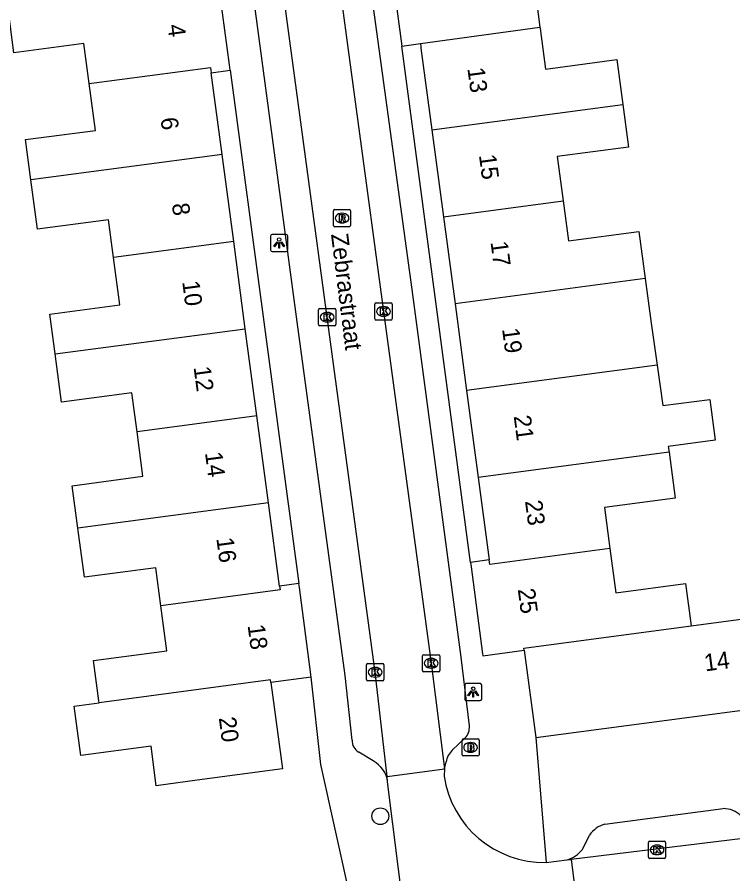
# Model space of a CAD drawing. Extents: x 163150 to 163546, y 380933 to 381635.
# Drawn here: x 163421.52 to 163463.18, y 381091.67 to 381141.54 of the extents above; entities that cross this region are included whole.
import ezdxf

# ---------------------------------------------------------------- set-up
doc = ezdxf.new("R2010")
doc.units = 0
for name, color, linetype in [('IMGEO_Boom', 7, 'Continuous'), ('IMGEO_Brandkraan', 7, 'Continuous'), ('IMGEO_Kolk', 7, 'Continuous'), ('IMGEO_Lichtpunt', 7, 'Continuous'), ('IMGEO_Openbare_ruimte_label', 7, 'Continuous'), ('IMGEO_Pand', 7, 'Continuous'), ('IMGEO_Pand_nummerreeks', 7, 'Continuous'), ('IMGEO_Rijbaan_lokaal_open', 7, 'Continuous'), ('IMGEO_Rioolput', 7, 'Continuous'), ('IMGEO_Voetpad_open', 7, 'Continuous')]:
    doc.layers.add(name, color=color, linetype=linetype)

msp = doc.modelspace()

# ---------------------------------------------------------------- linework, layer by layer
at = {"layer": 'IMGEO_Boom'}
msp.add_circle((163442.662, 381095.021), 0.489, dxfattribs=at)
at = {"layer": 'IMGEO_Brandkraan'}
for p, q in [((163447.491, 381099.529), (163448.343, 381099.529)), ((163447.416, 381098.603), (163447.416, 381099.455)), ((163447.904, 381099.309), (163447.929, 381099.309)), ((163448.417, 381099.455), (163448.417, 381098.603)), ((163448.343, 381098.529), (163447.491, 381098.529)), ((163447.927, 381098.749), (163447.902, 381098.749))]:
    msp.add_line(p, q, dxfattribs=at)
for points in [[(163447.491, 381099.529), (163448.343, 381099.529)], [(163447.416, 381098.603), (163447.416, 381099.455)], [(163447.764, 381099.229), (163447.764, 381098.829), (163447.977, 381098.829)], [(163447.995, 381099.229), (163447.764, 381099.229)], [(163447.943, 381099.148), (163447.889, 381099.148), (163447.889, 381099.072)], [(163447.889, 381099.072), (163447.942, 381099.072)], [(163447.951, 381098.996), (163447.889, 381098.996), (163447.889, 381098.915)], [(163448.417, 381099.455), (163448.417, 381098.603)], [(163448.343, 381098.529), (163447.491, 381098.529)], [(163447.889, 381098.915), (163447.951, 381098.915)]]:
    msp.add_lwpolyline(points, dxfattribs=at)
for centre, radius, start, end in [((163447.493, 381099.453), 0.0765, 91.552, 178.448), ((163447.493, 381099.453), 0.0765, 91.552, 178.448), ((163448.341, 381099.453), 0.0765, 1.552, 88.448), ((163448.341, 381099.453), 0.0765, 1.552, 88.448), ((163447.944, 381099.11), 0.0379, 267.8285, 90.9355), ((163447.952, 381098.955), 0.0404, 269.8759, 90.5077), ((163447.999, 381099.084), 0.145, 59.4692, 91.5367), ((163448.024, 381099.131), 0.0922, 285.5137, 58.1501), ((163448.029, 381098.939), 0.105, 301.3115, 78.989), ((163447.493, 381098.605), 0.0765, 181.552, 268.448), ((163447.493, 381098.605), 0.0765, 181.552, 268.448), ((163447.983, 381099.08), 0.251, 268.6676, 293.5347), ((163448.341, 381098.605), 0.0765, 271.552, 358.448), ((163448.341, 381098.605), 0.0765, 271.552, 358.448)]:
    msp.add_arc(centre, radius, start, end, dxfattribs=at)
for centre, major_axis, ratio, start_param, end_param in [((163447.903, 381099.029), (-0.387, 0.002), 0.722429, 4.712389, 7.853982), ((163447.928, 381099.029), (-0.39, 0.002), 0.717154, 1.570796, 4.712389)]:
    msp.add_ellipse(centre, major_axis=major_axis, ratio=ratio, start_param=start_param, end_param=end_param, dxfattribs=at)
at = {"layer": 'IMGEO_Kolk'}
for p, q in [((163442.421, 381124.91), (163443.273, 381124.91)), ((163439.065, 381123.649), (163439.065, 381124.501)), ((163439.14, 381124.575), (163439.992, 381124.575)), ((163440.066, 381124.501), (163440.066, 381123.649)), ((163442.346, 381123.984), (163442.346, 381124.836)), ((163442.834, 381124.69), (163442.859, 381124.69)), ((163443.347, 381124.836), (163443.347, 381123.984)), ((163439.553, 381124.355), (163439.578, 381124.355)), ((163443.273, 381123.91), (163442.421, 381123.91)), ((163442.857, 381124.13), (163442.832, 381124.13)), ((163439.992, 381123.575), (163439.14, 381123.575)), ((163439.576, 381123.795), (163439.551, 381123.795)), ((163445.122, 381103.499), (163445.122, 381104.351)), ((163445.197, 381104.425), (163446.049, 381104.425)), ((163445.61, 381104.205), (163445.635, 381104.205)), ((163446.123, 381104.351), (163446.123, 381103.499)), ((163441.862, 381102.98), (163441.862, 381103.832)), ((163441.937, 381103.906), (163442.789, 381103.906)), ((163442.35, 381103.686), (163442.375, 381103.686)), ((163442.863, 381103.832), (163442.863, 381102.98)), ((163445.633, 381103.645), (163445.608, 381103.645)), ((163442.373, 381103.126), (163442.348, 381103.126)), ((163446.049, 381103.425), (163445.197, 381103.425)), ((163442.789, 381102.906), (163441.937, 381102.906)), ((163458.269, 381092.637), (163458.269, 381093.489)), ((163458.344, 381093.563), (163459.196, 381093.563)), ((163459.27, 381093.489), (163459.27, 381092.637)), ((163458.757, 381093.343), (163458.782, 381093.343)), ((163459.196, 381092.563), (163458.344, 381092.563)), ((163458.78, 381092.783), (163458.755, 381092.783))]:
    msp.add_line(p, q, dxfattribs=at)
for points in [[(163442.421, 381124.91), (163443.273, 381124.91)], [(163439.065, 381123.649), (163439.065, 381124.501)], [(163439.14, 381124.575), (163439.992, 381124.575)], [(163440.066, 381124.501), (163440.066, 381123.649)], [(163442.346, 381123.984), (163442.346, 381124.836)], [(163442.667, 381124.61), (163442.79, 381124.61), (163442.79, 381124.459), (163442.92, 381124.61), (163443.084, 381124.61), (163442.938, 381124.459), (163443.091, 381124.21), (163442.939, 381124.21), (163442.854, 381124.374), (163442.79, 381124.307), (163442.79, 381124.21), (163442.667, 381124.21), (163442.667, 381124.61)], [(163443.347, 381124.836), (163443.347, 381123.984)], [(163439.386, 381124.275), (163439.509, 381124.275), (163439.509, 381124.124), (163439.639, 381124.275), (163439.803, 381124.275), (163439.657, 381124.124), (163439.81, 381123.875), (163439.658, 381123.875), (163439.573, 381124.039), (163439.509, 381123.972), (163439.509, 381123.875), (163439.386, 381123.875), (163439.386, 381124.275)], [(163443.273, 381123.91), (163442.421, 381123.91)], [(163439.992, 381123.575), (163439.14, 381123.575)], [(163445.122, 381103.499), (163445.122, 381104.351)], [(163445.197, 381104.425), (163446.049, 381104.425)], [(163445.443, 381104.125), (163445.566, 381104.125), (163445.566, 381103.974), (163445.696, 381104.125), (163445.86, 381104.125), (163445.714, 381103.974), (163445.867, 381103.725), (163445.715, 381103.725), (163445.63, 381103.889), (163445.566, 381103.822), (163445.566, 381103.725), (163445.443, 381103.725), (163445.443, 381104.125)], [(163446.123, 381104.351), (163446.123, 381103.499)], [(163441.862, 381102.98), (163441.862, 381103.832)], [(163441.937, 381103.906), (163442.789, 381103.906)], [(163442.183, 381103.606), (163442.306, 381103.606), (163442.306, 381103.455), (163442.436, 381103.606), (163442.6, 381103.606), (163442.454, 381103.455), (163442.607, 381103.206), (163442.455, 381103.206), (163442.37, 381103.37), (163442.306, 381103.303), (163442.306, 381103.206), (163442.183, 381103.206), (163442.183, 381103.606)], [(163442.863, 381103.832), (163442.863, 381102.98)], [(163446.049, 381103.425), (163445.197, 381103.425)], [(163442.789, 381102.906), (163441.937, 381102.906)], [(163458.269, 381092.637), (163458.269, 381093.489)], [(163458.344, 381093.563), (163459.196, 381093.563)], [(163459.27, 381093.489), (163459.27, 381092.637)], [(163458.59, 381093.263), (163458.713, 381093.263), (163458.713, 381093.112), (163458.843, 381093.263), (163459.007, 381093.263), (163458.861, 381093.112), (163459.014, 381092.863), (163458.862, 381092.863), (163458.777, 381093.027), (163458.713, 381092.96), (163458.713, 381092.863), (163458.59, 381092.863), (163458.59, 381093.263)], [(163459.196, 381092.563), (163458.344, 381092.563)]]:
    msp.add_lwpolyline(points, dxfattribs=at)
for centre, start, end in [((163442.423, 381124.834), 91.552, 178.448), ((163442.423, 381124.834), 91.552, 178.448), ((163443.271, 381124.834), 1.552, 88.448), ((163443.271, 381124.834), 1.552, 88.448), ((163439.142, 381124.499), 91.552, 178.448), ((163439.142, 381124.499), 91.552, 178.448), ((163439.99, 381124.499), 1.552, 88.448), ((163439.99, 381124.499), 1.552, 88.448), ((163442.423, 381123.986), 181.552, 268.448), ((163442.423, 381123.986), 181.552, 268.448), ((163443.271, 381123.986), 271.552, 358.448), ((163443.271, 381123.986), 271.552, 358.448), ((163439.142, 381123.651), 181.552, 268.448), ((163439.142, 381123.651), 181.552, 268.448), ((163439.99, 381123.651), 271.552, 358.448), ((163439.99, 381123.651), 271.552, 358.448), ((163445.199, 381104.349), 91.552, 178.448), ((163445.199, 381104.349), 91.552, 178.448), ((163446.047, 381104.349), 1.552, 88.448), ((163446.047, 381104.349), 1.552, 88.448), ((163441.939, 381103.83), 91.552, 178.448), ((163441.939, 381103.83), 91.552, 178.448), ((163442.787, 381103.83), 1.552, 88.448), ((163442.787, 381103.83), 1.552, 88.448), ((163445.199, 381103.501), 181.552, 268.448), ((163445.199, 381103.501), 181.552, 268.448), ((163446.047, 381103.501), 271.552, 358.448), ((163446.047, 381103.501), 271.552, 358.448), ((163441.939, 381102.982), 181.552, 268.448), ((163441.939, 381102.982), 181.552, 268.448), ((163442.787, 381102.982), 271.552, 358.448), ((163442.787, 381102.982), 271.552, 358.448), ((163458.346, 381093.487), 91.552, 178.448), ((163458.346, 381093.487), 91.552, 178.448), ((163459.194, 381093.487), 1.552, 88.448), ((163459.194, 381093.487), 1.552, 88.448), ((163458.346, 381092.639), 181.552, 268.448), ((163458.346, 381092.639), 181.552, 268.448), ((163459.194, 381092.639), 271.552, 358.448), ((163459.194, 381092.639), 271.552, 358.448)]:
    msp.add_arc(centre, 0.0765, start, end, dxfattribs=at)
for centre, major_axis, ratio, start_param, end_param in [((163442.833, 381124.41), (-0.387, 0.002), 0.722429, 4.712389, 7.853982), ((163442.858, 381124.41), (-0.39, 0.002), 0.717154, 1.570796, 4.712389), ((163439.552, 381124.075), (-0.387, 0.002), 0.722429, 4.712389, 7.853982), ((163439.577, 381124.075), (-0.39, 0.002), 0.717154, 1.570796, 4.712389), ((163445.609, 381103.925), (-0.387, 0.002), 0.722429, 4.712389, 7.853982), ((163445.634, 381103.925), (-0.39, 0.002), 0.717154, 1.570796, 4.712389), ((163442.349, 381103.406), (-0.387, 0.002), 0.722429, 4.712389, 7.853982), ((163442.374, 381103.406), (-0.39, 0.002), 0.717154, 1.570796, 4.712389), ((163458.756, 381093.063), (-0.387, 0.002), 0.722429, 4.712389, 7.853982), ((163458.781, 381093.063), (-0.39, 0.002), 0.717154, 1.570796, 4.712389)]:
    msp.add_ellipse(centre, major_axis=major_axis, ratio=ratio, start_param=start_param, end_param=end_param, dxfattribs=at)
at = {"layer": 'IMGEO_Lichtpunt'}
for p, q in [((163437.177, 381128.894), (163436.369, 381128.894)), ((163437.177, 381128.894), (163436.369, 381128.894)), ((163436.275, 381128.799), (163436.275, 381127.992)), ((163436.275, 381128.799), (163436.275, 381127.992)), ((163437.271, 381127.992), (163437.271, 381128.799)), ((163437.271, 381127.992), (163437.271, 381128.799)), ((163436.369, 381127.898), (163437.177, 381127.898)), ((163436.369, 381127.898), (163437.177, 381127.898)), ((163447.572, 381102.651), (163447.572, 381101.844)), ((163447.572, 381102.651), (163447.572, 381101.844)), ((163448.474, 381102.746), (163447.666, 381102.746)), ((163448.474, 381102.746), (163447.666, 381102.746)), ((163448.568, 381101.844), (163448.568, 381102.651)), ((163448.568, 381101.844), (163448.568, 381102.651)), ((163447.666, 381101.75), (163448.474, 381101.75)), ((163447.666, 381101.75), (163448.474, 381101.75))]:
    msp.add_line(p, q, dxfattribs=at)
for points in [[(163436.649, 381128.463), (163436.688, 381128.435), (163436.5, 381128.173), (163436.462, 381128.2), (163436.649, 381128.463)], [(163436.751, 381128.415), (163436.798, 381128.415), (163436.798, 381128.093), (163436.751, 381128.093), (163436.751, 381128.415)], [(163436.861, 381128.435), (163436.899, 381128.462), (163437.086, 381128.2), (163437.047, 381128.172), (163436.861, 381128.435)], [(163447.946, 381102.315), (163447.985, 381102.287), (163447.797, 381102.025), (163447.759, 381102.052), (163447.946, 381102.315)], [(163448.048, 381102.267), (163448.095, 381102.267), (163448.095, 381101.945), (163448.048, 381101.945), (163448.048, 381102.267)], [(163448.158, 381102.287), (163448.196, 381102.314), (163448.383, 381102.052), (163448.344, 381102.024), (163448.158, 381102.287)]]:
    msp.add_lwpolyline(points, dxfattribs=at)
for centre in [(163436.774, 381128.597), (163448.071, 381102.449)]:
    msp.add_circle(centre, 0.0994, dxfattribs=at)
for centre, start, end in [((163436.369, 381128.799), 90, 180), ((163436.369, 381128.799), 90, 180), ((163437.177, 381128.799), 0, 90), ((163437.177, 381128.799), 0, 90), ((163436.369, 381127.992), 180, 270), ((163436.369, 381127.992), 180, 270), ((163437.177, 381127.992), 270, 0), ((163437.177, 381127.992), 270, 360), ((163447.666, 381102.651), 90, 180), ((163447.666, 381102.651), 90, 180), ((163448.474, 381102.651), 0, 90), ((163448.474, 381102.651), 0, 90), ((163447.666, 381101.844), 180, 270), ((163447.666, 381101.844), 180, 270), ((163448.474, 381101.844), 270, 0), ((163448.474, 381101.844), 270, 360)]:
    msp.add_arc(centre, 0.0946, start, end, dxfattribs=at)
at = {"layer": 'IMGEO_Pand'}
for points in [[(163455.453, 381146.52), (163455.794, 381143.954), (163455.402, 381143.902), (163451.629, 381143.4), (163451.954, 381140.957)], [(163443.183, 381145.265), (163443.226, 381144.943), (163443.904, 381139.851)], [(163433.927, 381138.448), (163433.885, 381138.765), (163433.211, 381143.836), (163433.187, 381144.015)], [(163425.72, 381137.678), (163425.411, 381140.001), (163421.332, 381139.458), (163421.009, 381141.888), (163420.967, 381142.206)], [(163444.992, 381140.001), (163451.954, 381140.957)], [(163451.954, 381140.957), (163451.964, 381140.88), (163452.279, 381138.518), (163456.436, 381139.072), (163456.785, 381136.454)], [(163443.904, 381139.851), (163444.992, 381140.001)], [(163444.992, 381140.001), (163445.018, 381139.81), (163445.027, 381139.741), (163445.662, 381134.974)], [(163425.72, 381137.678), (163432.776, 381138.617), (163432.818, 381138.301)], [(163432.818, 381138.301), (163433.927, 381138.448)], [(163433.45, 381133.547), (163432.818, 381138.301)], [(163422.325, 381132.066), (163422.013, 381134.41), (163426.082, 381134.951), (163425.72, 381137.678)], [(163445.662, 381134.974), (163456.785, 381136.454)], [(163456.785, 381136.454), (163457.115, 381133.977), (163452.958, 381133.423), (163453.302, 381130.842)], [(163445.662, 381134.974), (163446.335, 381129.915)], [(163433.45, 381133.547), (163422.325, 381132.066)], [(163434.125, 381128.475), (163433.45, 381133.547)], [(163427.131, 381127.544), (163426.838, 381129.747), (163422.706, 381129.197), (163422.325, 381132.066)], [(163446.335, 381129.915), (163453.302, 381130.842)], [(163453.302, 381130.842), (163453.612, 381128.512), (163457.717, 381129.058), (163458.08, 381126.332)], [(163446.335, 381129.915), (163447.009, 381124.858)], [(163434.125, 381128.475), (163427.131, 381127.544)], [(163434.799, 381123.405), (163434.125, 381128.475)], [(163423.729, 381121.932), (163423.42, 381124.251), (163427.497, 381124.793), (163427.131, 381127.544)], [(163458.08, 381126.332), (163447.009, 381124.858)], [(163458.08, 381126.332), (163458.428, 381123.722), (163458.776, 381121.276)], [(163447.009, 381124.858), (163447.682, 381119.8)], [(163423.729, 381121.932), (163434.799, 381123.405)], [(163435.473, 381118.335), (163434.799, 381123.405)], [(163428.498, 381117.406), (163428.198, 381119.666), (163424.103, 381119.122), (163423.729, 381121.932)], [(163458.776, 381121.276), (163447.682, 381119.8)], [(163458.776, 381121.276), (163459.11, 381118.928), (163461.838, 381119.291), (163462.153, 381116.919), (163459.426, 381116.556), (163459.47, 381116.223)], [(163447.682, 381119.8), (163448.355, 381114.744)], [(163435.473, 381118.335), (163428.498, 381117.406)], [(163436.148, 381113.265), (163435.473, 381118.335)], [(163425.057, 381111.788), (163424.728, 381114.263), (163428.843, 381114.81), (163428.498, 381117.406)], [(163459.47, 381116.223), (163448.355, 381114.744)], [(163459.47, 381116.223), (163459.827, 381113.544), (163455.707, 381112.996), (163456.024, 381110.617)], [(163448.355, 381114.744), (163448.995, 381109.94)], [(163436.148, 381113.265), (163425.057, 381111.788)], [(163436.793, 381108.412), (163436.148, 381113.265)], [(163429.89, 381107.271), (163429.596, 381109.484), (163425.437, 381108.931), (163425.057, 381111.788)], [(163456.024, 381110.617), (163449.029, 381109.686), (163448.995, 381109.94)], [(163456.024, 381110.617), (163456.369, 381108.03), (163460.426, 381108.57), (163460.755, 381106.1)], [(163448.995, 381109.94), (163447.91, 381109.796)], [(163447.91, 381109.796), (163447.944, 381109.542), (163448.617, 381104.484), (163448.633, 381104.366), (163451.038, 381104.686)], [(163437.919, 381108.562), (163436.793, 381108.412)], [(163438.642, 381103.121), (163438.622, 381103.273), (163437.948, 381108.344), (163437.919, 381108.562)], [(163436.793, 381108.412), (163436.822, 381108.194), (163429.89, 381107.271)], [(163426.285, 381101.63), (163426.269, 381101.746), (163425.958, 381104.083), (163430.238, 381104.652), (163429.89, 381107.271)], [(163460.755, 381106.1), (163465.255, 381106.699), (163465.271, 381106.578), (163470.116, 381107.225)], [(163451.038, 381104.686), (163451.022, 381104.804), (163460.755, 381106.1)], [(163451.038, 381104.686), (163451.716, 381099.596)], [(163436.291, 381102.809), (163436.271, 381102.96), (163426.285, 381101.63)], [(163438.642, 381103.121), (163436.291, 381102.809)], [(163436.291, 381102.809), (163436.961, 381097.771), (163432.005, 381097.112), (163429.622, 381096.795), (163429.315, 381099.099), (163425.22, 381098.555), (163424.837, 381101.437), (163426.285, 381101.63)], [(163451.716, 381099.596), (163473.559, 381102.505)]]:
    msp.add_lwpolyline(points, dxfattribs=at)
at = {"layer": 'IMGEO_Rijbaan_lokaal_open'}
for points in [[(163443.052, 381097.331), (163442.364, 381103.407), (163439.567, 381124.075), (163436.817, 381144.486), (163434.274, 381163.073), (163433.722, 381167.087)], [(163437.11, 381166.833), (163437.609, 381163.446), (163439.859, 381146.552), (163442.846, 381124.409), (163445.622, 381103.925), (163446.393, 381097.771)], [(163443.052, 381097.331), (163446.393, 381097.771)], [(163446.393, 381097.771), (163446.371, 381097.362)], [(163443.087, 381097.024), (163443.052, 381097.331)], [(163444.032, 381089.471), (163443.087, 381097.024)], [(163465.527, 381093.942), (163453.767, 381092.507)], [(163453.528, 381092.478), (163453.767, 381092.507)], [(163453.767, 381092.507), (163454.236, 381088.812)], [(163452.309, 381092.324), (163453.528, 381092.478)]]:
    msp.add_lwpolyline(points, dxfattribs=at)
msp.add_arc((163452.219, 381098.237), 5.913, 188.5065, 270.8687, dxfattribs=at)
at = {"layer": 'IMGEO_Rioolput'}
for p, q in [((163439.931, 381129.417), (163439.931, 381130.269)), ((163440.006, 381130.343), (163440.858, 381130.343)), ((163440.419, 381130.123), (163440.444, 381130.123)), ((163440.932, 381130.269), (163440.932, 381129.417)), ((163440.442, 381129.563), (163440.417, 381129.563)), ((163440.858, 381129.343), (163440.006, 381129.343))]:
    msp.add_line(p, q, dxfattribs=at)
for points in [[(163439.931, 381129.417), (163439.931, 381130.269)], [(163440.006, 381130.343), (163440.858, 381130.343)], [(163440.52, 381130.041), (163440.268, 381130.043), (163440.268, 381129.643)], [(163440.446, 381129.962), (163440.392, 381129.962), (163440.392, 381129.881)], [(163440.932, 381130.269), (163440.932, 381129.417)], [(163440.268, 381129.643), (163440.392, 381129.643), (163440.392, 381129.805), (163440.403, 381129.805)], [(163440.392, 381129.881), (163440.444, 381129.881)], [(163440.45, 381129.776), (163440.521, 381129.643), (163440.661, 381129.643), (163440.596, 381129.769)], [(163440.858, 381129.343), (163440.006, 381129.343)]]:
    msp.add_lwpolyline(points, dxfattribs=at)
for centre, radius, start, end in [((163440.008, 381130.267), 0.0765, 91.552, 178.448), ((163440.008, 381130.267), 0.0765, 91.552, 178.448), ((163440.452, 381129.866), 0.0964, 77.0061, 93.1865), ((163440.466, 381129.923), 0.0378, 276.6634, 79.6772), ((163440.519, 381129.931), 0.109, 350.3612, 89.416), ((163440.517, 381129.931), 0.112, 277.5842, 350.9817), ((163440.856, 381130.267), 0.0765, 1.552, 88.448), ((163440.856, 381130.267), 0.0765, 1.552, 88.448), ((163440.008, 381129.419), 0.0765, 181.552, 268.448), ((163440.008, 381129.419), 0.0765, 181.552, 268.448), ((163440.402, 381129.752), 0.0533, 26.0293, 88.6989), ((163440.428, 381130.07), 0.19, 274.7715, 282.9687), ((163440.501, 381129.716), 0.108, 29.5134, 73.7905), ((163440.856, 381129.419), 0.0765, 271.552, 358.448), ((163440.856, 381129.419), 0.0765, 271.552, 358.448)]:
    msp.add_arc(centre, radius, start, end, dxfattribs=at)
for centre, major_axis, ratio, start_param, end_param in [((163440.418, 381129.843), (-0.387, 0.002), 0.722429, 4.712389, 7.853982), ((163440.443, 381129.843), (-0.39, 0.002), 0.717154, 1.570796, 4.712389)]:
    msp.add_ellipse(centre, major_axis=major_axis, ratio=ratio, start_param=start_param, end_param=end_param, dxfattribs=at)
at = {"layer": 'IMGEO_Voetpad_open'}
for points in [[(163441.023, 381099.453), (163440.624, 381103.205), (163437.819, 381123.795), (163435.103, 381144.087), (163432.575, 381162.741), (163431.927, 381167.376)], [(163447.843, 381100.283), (163447.373, 381104.275), (163444.508, 381125.688), (163441.66, 381146.506), (163439.349, 381163.632), (163439.266, 381164.329)], [(163447.91, 381109.796), (163443.904, 381139.851)], [(163433.927, 381138.448), (163437.919, 381108.562)], [(163440.974, 381089.977), (163439.201, 381098.033), (163438.642, 381103.121)], [(163446.847, 381098.871), (163447.582, 381099.571)], [(163451.716, 381099.596), (163452.309, 381092.324)], [(163442.245, 381098.238), (163441.413, 381098.76)], [(163446.393, 381097.771), (163446.49, 381098.179)], [(163455.74, 381094.559), (163462.613, 381095.463)], [(163454.421, 381093.09), (163454.837, 381093.923)]]:
    msp.add_lwpolyline(points, dxfattribs=at)
for centre, radius, start, end in [((163446.997, 381100.189), 0.852, 313.4296, 6.3073), ((163441.721, 381099.389), 0.7, 174.7822, 243.9569), ((163447.829, 381097.926), 1.363, 136.1101, 169.3118), ((163441.503, 381096.824), 1.597, 7.1894, 62.299), ((163462.643, 381094.032), 1.432, 44.3794, 91.1946), ((163456.186, 381092.967), 1.653, 105.6459, 144.6696), ((163453.03, 381094.163), 1.757, 286.4786, 322.3695)]:
    msp.add_arc(centre, radius, start, end, dxfattribs=at)

# ---------------------------------------------------------------- texts
at = {"layer": 'IMGEO_Openbare_ruimte_label'}
msp.add_text('Zebrastraat', height=1, rotation=277.125, dxfattribs=at).set_placement((163439.787, 381128.901))
at = {"layer": 'IMGEO_Pand_nummerreeks'}
for s, rotation, p in [('4', 277.5743, (163430.269, 381141.073)), ('13', 277.5858, (163447.726, 381138.563)), ('6', 277.5743, (163429.862, 381135.652)), ('15', 277.5844, (163448.399, 381133.506)), ('8', 277.5754, (163430.524, 381130.665)), ('17', 277.5844, (163449.073, 381128.449)), ('10', 277.5754, (163431.127, 381126.141)), ('19', 277.5844, (163449.746, 381123.391)), ('12', 277.5754, (163431.788, 381121.165)), ('21', 277.5844, (163450.422, 381118.312)), ('14', 277.5754, (163432.452, 381116.181)), ('23', 277.5858, (163451.081, 381113.367)), ('16', 277.5743, (163433.114, 381111.199)), ('25', 277.5858, (163450.66, 381108.233)), ('18', 277.5686, (163434.933, 381106.136)), ('14', 7.586, (163461.576, 381103.451)), ('20', 277.5743, (163433.256, 381100.749))]:
    msp.add_text(s, height=1, rotation=rotation, dxfattribs=at).set_placement(p)

doc.saveas('drawing.dxf')
